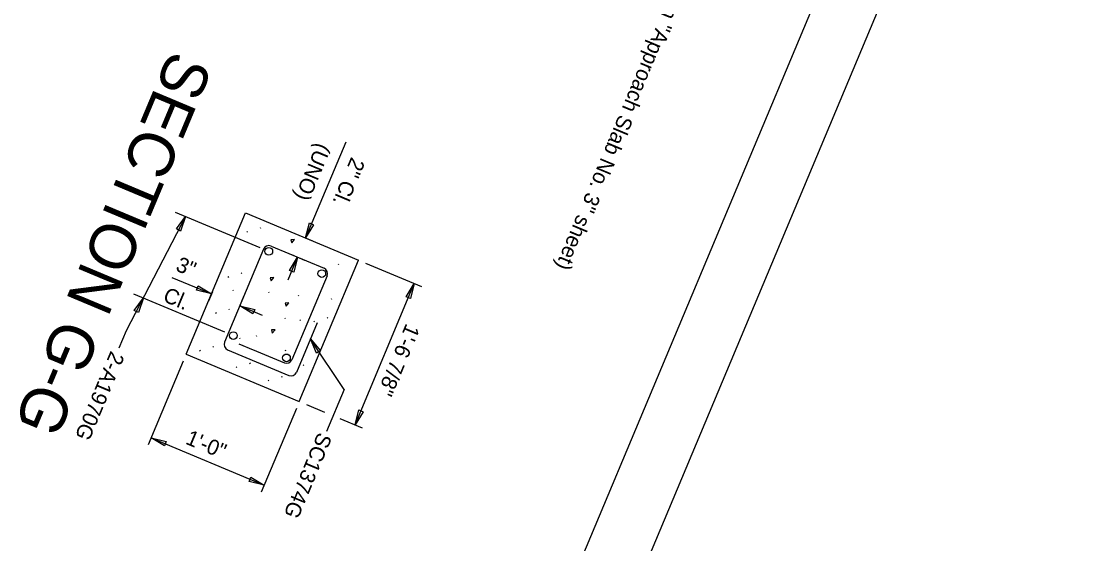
# Model space of a CAD drawing. Extents: x 1968564 to 1968711, y 796599 to 796794.
# Drawn here: x 1968641.02 to 1968675.87, y 796638.67 to 796655.71 of the extents above; entities that cross this region are included whole.
import ezdxf

# ---------------------------------------------------------------- set-up
doc = ezdxf.new("R2010")
doc.units = 0
for name, color, linetype in [('BR_AUTO DIMENSION', 7, 'Continuous'), ('BR_BORDER LINES', 7, 'Continuous'), ('BR_CONCRETE', 7, 'Continuous'), ('BR_DETAILS', 7, 'Continuous'), ('BR_REBAR', 7, 'Continuous'), ('BR_TEXT', 7, 'Continuous'), ('Level 31', 7, 'Continuous')]:
    doc.layers.add(name, color=color, linetype=linetype)

msp = doc.modelspace()

# ---------------------------------------------------------------- linework, layer by layer
at = {"layer": 'BR_AUTO DIMENSION'}
for p, q in [((1968651.604, 796651.775), (1968650.291, 796648.645)), ((1968646.033, 796649.492), (1968648.794, 796648.334)), ((1968646.377, 796649.347), (1968644.439, 796645.612)), ((1968650.07, 796648.738), (1968650.522, 796648.548)), ((1968649.828, 796648.103), (1968650.259, 796647.922)), ((1968649.719, 796647.281), (1968650.028, 796648.019)), ((1968652.251, 796647.823), (1968654.069, 796647.06)), ((1968645.924, 796647.361), (1968647.22, 796646.818)), ((1968651.905, 796642.546), (1968653.839, 796647.157)), ((1968644.677, 796646.828), (1968647.641, 796645.585)), ((1968647.249, 796646.886), (1968647.123, 796646.587)), ((1968648.28, 796646.759), (1968648.046, 796646.2)), ((1968648.88, 796646.121), (1968648.142, 796646.431)), ((1968644.439, 796645.612), (1968644.202, 796645.048)), ((1968651.553, 796643.704), (1968650.477, 796645.307)), ((1968646.301, 796644.626), (1968645.156, 796641.896)), ((1968651.553, 796643.704), (1968650.978, 796642.333)), ((1968650.317, 796643.212), (1968650.909, 796642.964)), ((1968649.99, 796643.078), (1968648.845, 796640.349)), ((1968651.403, 796642.757), (1968652.135, 796642.45)), ((1968645.253, 796642.127), (1968648.941, 796640.58))]:
    msp.add_line(p, q, dxfattribs=at)
for points in [[(1968646.08, 796648.938), (1968646.377, 796649.347), (1968646.213, 796648.869)], [(1968650.554, 796649.077), (1968650.291, 796648.645), (1968650.415, 796649.135)], [(1968649.766, 796647.587), (1968650.028, 796648.019), (1968649.904, 796647.529)], [(1968646.788, 796647.08), (1968647.22, 796646.818), (1968646.73, 796646.942)], [(1968653.576, 796646.725), (1968653.839, 796647.157), (1968653.714, 796646.667)], [(1968644.703, 796646.284), (1968645, 796646.693), (1968644.836, 796646.215)], [(1968648.574, 796646.168), (1968648.142, 796646.431), (1968648.632, 796646.307)], [(1968650.651, 796644.888), (1968650.448, 796645.35), (1968650.778, 796644.968)], [(1968652.167, 796642.978), (1968651.905, 796642.546), (1968652.029, 796643.036)], [(1968645.685, 796641.864), (1968645.253, 796642.127), (1968645.743, 796642.003)], [(1968648.509, 796640.842), (1968648.941, 796640.58), (1968648.451, 796640.704)]]:
    msp.add_lwpolyline(points, close=True, dxfattribs=at)
at = {"layer": 'BR_BORDER LINES'}
msp.add_line((1968643.927, 796601.539), (1968696.012, 796725.723), dxfattribs=at)
at = {"layer": 'BR_CONCRETE'}
for p, q in [((1968646.398, 796644.856), (1968648.331, 796649.467)), ((1968648.331, 796649.467), (1968652.02, 796647.92)), ((1968650.086, 796643.309), (1968652.02, 796647.92)), ((1968646.398, 796644.856), (1968650.086, 796643.309))]:
    msp.add_line(p, q, dxfattribs=at)
at = {"layer": 'BR_DETAILS'}
for p, q in [((1968648.376, 796648.861), (1968648.393, 796648.836)), ((1968648.808, 796648.985), (1968648.824, 796648.96)), ((1968651.35, 796647.804), (1968651.366, 796647.779)), ((1968647.757, 796647.386), (1968647.774, 796647.361)), ((1968648.189, 796647.51), (1968648.206, 796647.485)), ((1968647.912, 796646.955), (1968647.928, 796646.93)), ((1968649.076, 796646.888), (1968649.092, 796646.863)), ((1968650.046, 796646.779), (1968650.062, 796646.754)), ((1968651.124, 796646.674), (1968651.141, 796646.649)), ((1968647.783, 796646.336), (1968647.8, 796646.311)), ((1968647.352, 796646.211), (1968647.368, 796646.186)), ((1968649.609, 796646.039), (1968649.625, 796646.014)), ((1968650.104, 796645.976), (1968650.12, 796645.951)), ((1968650.564, 796645.931), (1968650.581, 796645.906)), ((1968650.996, 796646.056), (1968651.012, 796646.031)), ((1968648.13, 796645.391), (1968648.147, 796645.366)), ((1968648.677, 796645.467), (1968648.694, 796645.442)), ((1968646.835, 796644.98), (1968646.852, 796644.955)), ((1968647.267, 796645.105), (1968647.283, 796645.08)), ((1968649.624, 796644.993), (1968649.64, 796644.968)), ((1968648.463, 796644.568), (1968648.48, 796644.543)), ((1968648.031, 796644.443), (1968648.048, 796644.418)), ((1968650.215, 796644.506), (1968650.231, 796644.481)), ((1968649.072, 796644.007), (1968649.088, 796643.982)), ((1968649.504, 796644.132), (1968649.52, 796644.107))]:
    msp.add_line(p, q, dxfattribs=at)
for points in [[(1968649.93, 796648.595), (1968649.815, 796648.589), (1968649.84, 796648.488), (1968649.93, 796648.595)], [(1968649.254, 796647.352), (1968649.139, 796647.346), (1968649.164, 796647.245), (1968649.254, 796647.352)], [(1968649.746, 796646.525), (1968649.63, 796646.519), (1968649.656, 796646.419), (1968649.746, 796646.525)], [(1968649.294, 796645.651), (1968649.178, 796645.645), (1968649.204, 796645.544), (1968649.294, 796645.651)]]:
    msp.add_lwpolyline(points, dxfattribs=at)
at = {"layer": 'BR_REBAR'}
for p, q in [((1968649.164, 796648.382), (1968650.893, 796647.657)), ((1968648.919, 796648.281), (1968647.645, 796645.246)), ((1968650.993, 796647.411), (1968649.845, 796644.673)), ((1968650.667, 796645.872), (1968649.991, 796644.262)), ((1968647.746, 796645), (1968649.746, 796644.162)), ((1968648.117, 796645.195), (1968648.579, 796645.001)), ((1968648.558, 796645.01), (1968649.6, 796644.573))]:
    msp.add_line(p, q, dxfattribs=at)
for centre in [(1968649.091, 796648.209), (1968650.821, 796647.484), (1968647.934, 796645.462), (1968649.668, 796644.735)]:
    msp.add_circle(centre, 0.125, dxfattribs=at)
for centre, start, end in [((1968649.091, 796648.209), 67.246, 157.246), ((1968650.821, 796647.484), 337.246, 67.246), ((1968647.818, 796645.173), 157.246, 247.246), ((1968649.672, 796644.746), 247.246, 337.246), ((1968649.818, 796644.334), 247.246, 337.246)]:
    msp.add_arc(centre, 0.188, start, end, dxfattribs=at)
at = {"layer": 'Level 31'}
msp.add_lwpolyline([(1968619.541, 796765.748), (1968563.846, 796632.955), (1968644.997, 796598.919), (1968700.693, 796731.712)], close=True, dxfattribs=at)

# ---------------------------------------------------------------- texts
at = {"layer": 'BR_AUTO DIMENSION'}
for s, rotation, p in [('(UNO)', 247.246, (1968650.675, 796651.774)), ('2" Cl. ', 247.246, (1968651.784, 796651.309)), ('3"', 337.246, (1968646.021, 796647.592)), ('1\'-6 7/8"', 247.246, (1968653.575, 796645.882)), ('1\'-0"', 337.246, (1968646.343, 796641.941))]:
    msp.add_text(s, height=0.5, rotation=rotation, dxfattribs=at).set_placement(p)
at = {"layer": 'BR_TEXT'}
for s, height, rotation, p in [('Chamfer (See Detail "A" on "Approach Slab No. 3" sheet)', 0.49995, 247.246, (1968665.001, 796663.364)), ('SECTION G-G', 1.5, 247.246, (1968645.898, 796654.826)), ('Cl.', 0.5, 337.246, (1968645.604, 796646.596)), ('2-A1970G', 0.4999, 247.246, (1968643.937, 796644.985)), ('SC1374G', 0.4999, 247.246, (1968650.706, 796642.336))]:
    msp.add_text(s, height=height, rotation=rotation, dxfattribs=at).set_placement(p)

doc.saveas('drawing.dxf')
